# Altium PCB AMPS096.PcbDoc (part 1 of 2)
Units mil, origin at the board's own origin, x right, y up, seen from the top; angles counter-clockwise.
Board outline 2170 x 3820 mil, 2 copper layers (Top Layer, Bottom Layer), stack 62 mil thick; 82 components, 27 nets, 181 pads, 486 vias.
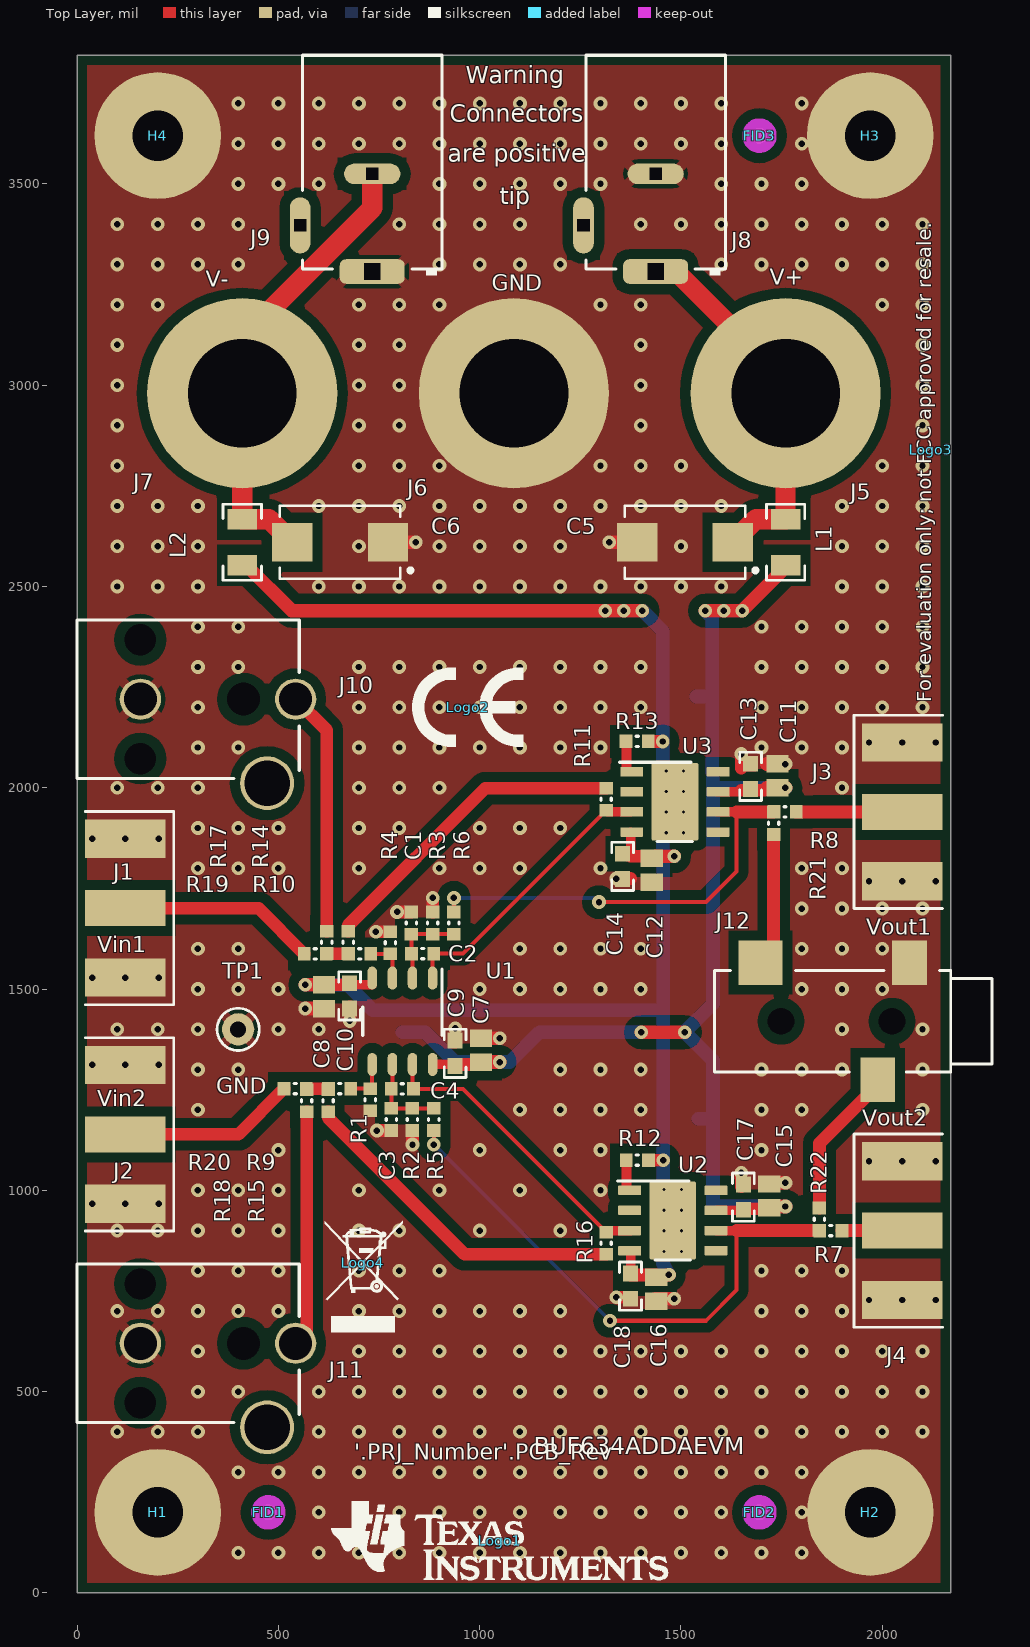
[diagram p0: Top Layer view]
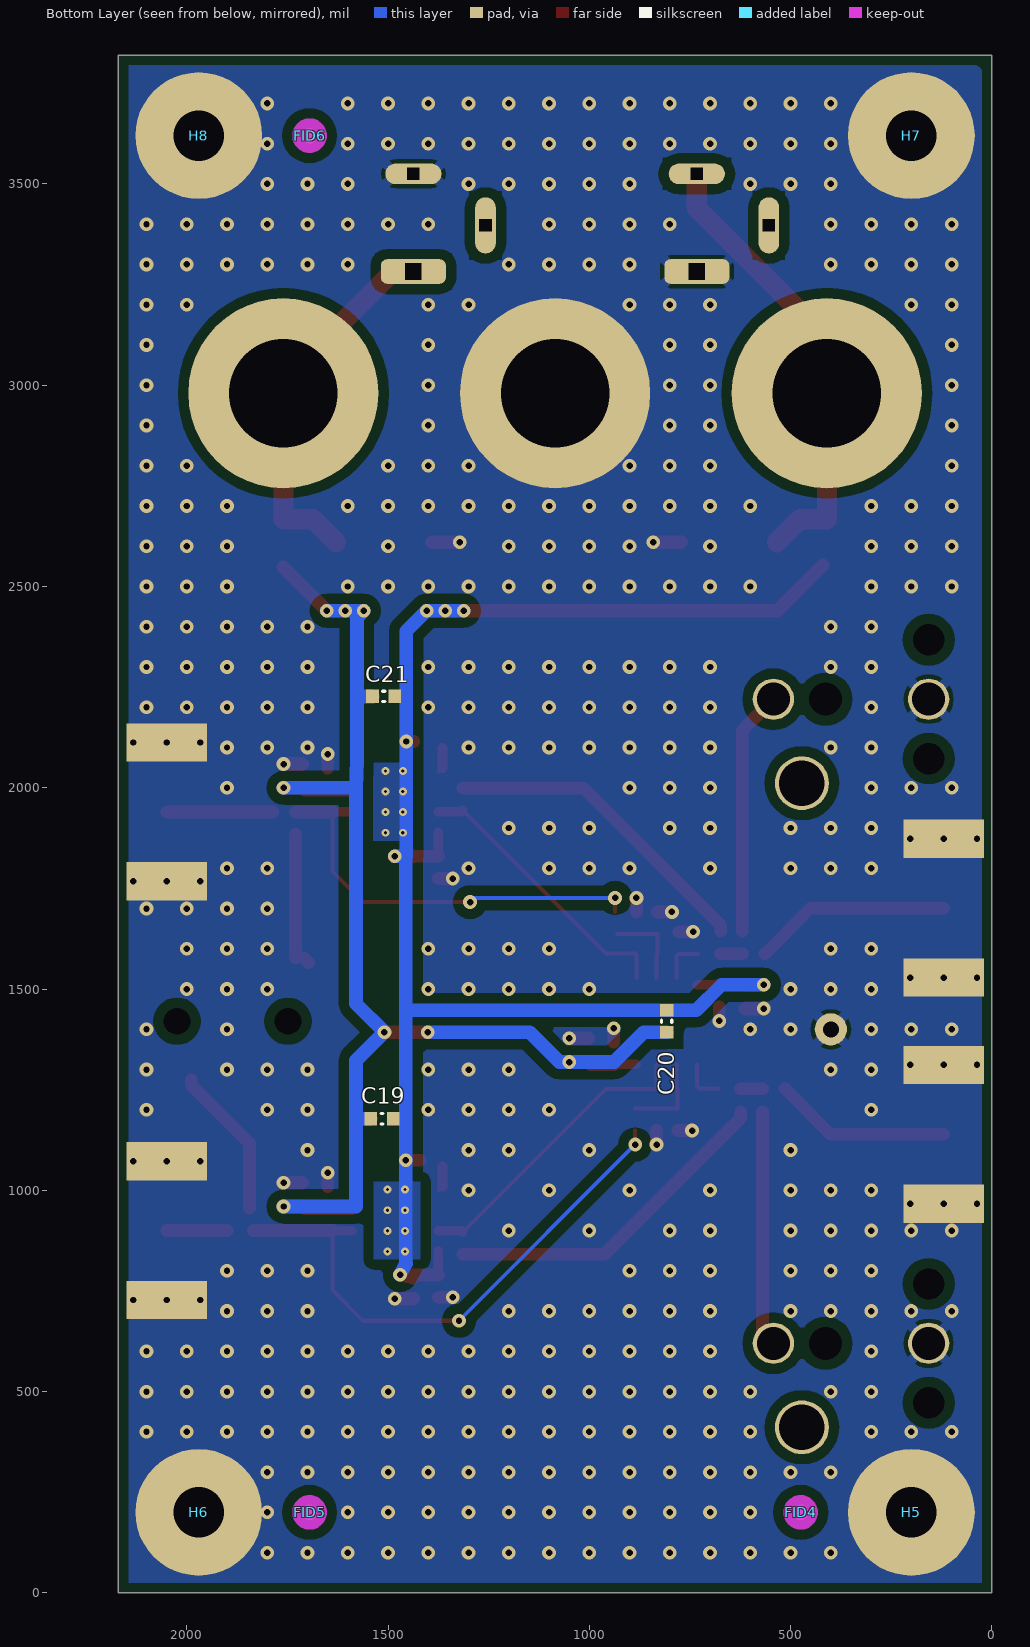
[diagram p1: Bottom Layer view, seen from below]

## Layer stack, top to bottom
Top Solder: solder mask 0.4, Solder Resist, Dk 3.5
Top Layer: signal copper 1.4
Dielectric1: core 59.2, FR-4 High Tg, Dk 4.8
Bottom Layer: signal copper 1.4
Bottom Solder: solder mask 0.4, Solder Resist, Dk 3.5

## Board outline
0,0 2170,0 2170,3820 0,3820

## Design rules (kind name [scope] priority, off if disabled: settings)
AcuteAngle [All] p1: minimum=4.50000000000000E+0001 checktracksonly=FALSE
AssemblyTestPointUsage [All] p1: valid=2
BoardOutlineClearance BoardOutlineClearance_MountingHoles [OnCopper and InComponentClass('Mounting Holes')] p1: gap=40 ignorepadtopadclearanceinfootprint=FALSE
BoardOutlineClearance BoardOutlineClearance_Poly [OnCopper and IsPoly] p2: gap=25 ignorepadtopadclearanceinfootprint=FALSE
BoardOutlineClearance [OnCopper and Not InComponentClass('Logo') and not InComponentClass('FiducialMark') and not InRegion(1000,500,4000,800) and not InPoly] p3: gap=20 ignorepadtopadclearanceinfootprint=FALSE
Clearance Clearance_FiducialMark [InComponent('FID*') vs InComponent('FID*')] p1: gap=0 ignorepadtopadclearanceinfootprint=FALSE
Clearance Clearance_Keepouts [((IsTrack Or IsArc) And Not InPoly) And IsFree and IsKeepOut vs ((IsTrack Or IsArc) And Not InPoly) And IsFree and IsKeepOut] p2: gap=0 ignorepadtopadclearanceinfootprint=FALSE
Clearance Clearance_Poly [InPolygon] p3: gap=25 ignorepadtopadclearanceinfootprint=FALSE except(0: Arc-Hole Track-Hole SMDPad-Hole THPad-Hole Via-Hole Fill-Hole Poly-Hole Region-Hole Text-Hole)
Clearance [All] p4: gap=7.87 ignorepadtopadclearanceinfootprint=FALSE except(0: Arc-Hole Track-Hole SMDPad-Hole THPad-Hole Via-Hole Fill-Hole Poly-Hole Region-Hole Text-Hole)
ComponentClearance ComponentClearance_R7_R22 [InComponent('R7') OR InComponent('R22')] p1: gap=0 collisioncheckmode=3 verticalgap=0 showdistances=FALSE
ComponentClearance ComponentClearance_R8_R21 [InComponent('R8') OR InComponent('R21')] p2: gap=0 collisioncheckmode=3 verticalgap=0 showdistances=FALSE
ComponentClearance ComponentClearance_R9_R16 [InComponent('R9') OR InComponent('R16')] p3: gap=0 collisioncheckmode=3 verticalgap=0 showdistances=FALSE
ComponentClearance ComponentClearance_R10_R15 [InComponent('R10') OR InComponent('R15')] p4: gap=0 collisioncheckmode=3 verticalgap=0 showdistances=FALSE
ComponentClearance ComponentClearance_R17_R19 [InComponent('R17') OR InComponent('R19')] p5: gap=0 collisioncheckmode=3 verticalgap=0 showdistances=FALSE
ComponentClearance ComponentClearance_R18_R20 [InComponent('R18') OR InComponent('R20')] p6: gap=0 collisioncheckmode=3 verticalgap=0 showdistances=FALSE
ComponentClearance ComponentClearance_MountingHoles_FiducialMarks [InComponentClass('Mounting Holes') vs InComponentClass('FiducialMark')] p7: gap=50 collisioncheckmode=3 verticalgap=10 showdistances=FALSE
ComponentClearance ComponentClearance_Shunt [InComponentClass('Header') vs InComponentClass('Shunt')] p8: gap=0 collisioncheckmode=3 verticalgap=0 showdistances=FALSE
ComponentClearance ComponentClearance_Logo [InComponentClass('Logo')] p9: gap=50 collisioncheckmode=3 verticalgap=10 showdistances=FALSE
ComponentClearance ComponentClearance_ScrewToNut [(HasFootprint('NY PMS 440 0025 PH')) vs (HasFootprint('Keystone_1902C'))] p10: gap=5 collisioncheckmode=3 verticalgap=10 showdistances=FALSE
ComponentClearance ComponentClearance_MountingHoles [InComponentClass('Mounting Holes')] p11: gap=50 collisioncheckmode=3 verticalgap=100000 showdistances=FALSE
ComponentClearance ComponentClearance_SmallPassives [HasFootprint('0201*') or HasFootprint('0402*') or HasFootprint('0508') or HasFootprint('0603*') or HasFootprint('0612') or HasFootprint('0805*') or HasFootprint('0815*') or HasFootprint('0830*') or HasFootprint('1206*') or HasFootprint('1210*') or HasFootprint('1808*') or HasFootprint('1812*') or HasFootprint('1825*') or HasFootprint('2010*') or HasFootprint('2220*') or HasFootprint('2225*') or HasFootprint('2512*') or HasFootprint('2728*') or HasFootprint('3518*') or HasFootprint('D0008A*') vs HasFootprint('0201*') or HasFootprint('0402*') or HasFootprint('0508') or HasFootprint('0603*') or HasFootprint('0612') or HasFootprint('0805*') or HasFootprint('0815*') or HasFootprint('0830*') or HasFootprint('1206*') or HasFootprint('1210*') or HasFootprint('1808*') or HasFootprint('1812*') or HasFootprint('1825*') or HasFootprint('2010*') or HasFootprint('2220*') or HasFootprint('2225*') or HasFootprint('2512*') or HasFootprint('2728*') or HasFootprint('3518*') or HasFootprint('D0008A*')] p12: gap=14.96 collisioncheckmode=3 verticalgap=10 showdistances=FALSE
ComponentClearance ComponentClearance_THtoSMT [IsThruComponent vs IsSMTComponent] p13: gap=40 collisioncheckmode=3 verticalgap=30 showdistances=FALSE
ComponentClearance ComponentClearance_THtoTH [IsThruComponent vs IsThruComponent] p14: gap=30 collisioncheckmode=3 verticalgap=30 showdistances=FALSE
ComponentClearance [All] p15: gap=30 collisioncheckmode=3 verticalgap=10 showdistances=FALSE
DiffPairsRouting [All] p1: maxlimit=100 minlimit=10 mostfreqgap=10 toplayer_minwidth=15 toplayer_maxwidth=15 toplayer_prefwidth=15 bottomlayer_minwidth=15 bottomlayer_maxwidth=15 bottomlayer_prefwidth=15 maxuncoupledlength=1000
FabricationTestPointUsage TestPointUsage [All] p1: valid=2 allowmultiple=FALSE
FabricationTestpoint Testpoint [All] p1: side=3 testpointundercomponent=TRUE minsize=40 maxsize=100 preferedsize=60 minholesize=0 maxholesize=40 preferedholesize=32 testpointgrid=1 allowsidetop=TRUE allowsidebottom=TRUE usegrid=TRUE gridtolerance=0.01
FanoutControl Fanout_LCC [IsLCC] p1: bgadir=Out bgaviamode=Centered fanoutstyle=Auto fanoutdirection=Alternating viagrid=1 // Fanout_LCC (Default Rule)
FanoutControl Fanout_BGA [IsBGA] p2: bgadir=Out bgaviamode=Centered fanoutstyle=Auto fanoutdirection=Alternating viagrid=1 // Fanout_BGA (Default Rule)
FanoutControl Fanout_Default [All] p4: bgadir=Out bgaviamode=Centered fanoutstyle=Auto fanoutdirection=Alternating viagrid=1 // Fanout_Default (Default Rule)
FanoutControl Fanout_Small [(CompPinCount < 5)] p5: bgadir=Out bgaviamode=Centered fanoutstyle=Auto fanoutdirection=OutThenIn viagrid=1 // Fanout_Small (Default Rule)
HoleSize [All] p1: absolutevalues=TRUE maxlimit=270 minlimit=7.87 maxpercent=80.000 minpercent=20.000
MinimumAnnularRing MinimumAnnularRing_J8_J9 [(InComponent('J8') OR InComponent('J9'))] p1: minimumring=3.87
MinimumAnnularRing MinimumAnnularRing_ThermalPadVias [IsVia and InAnyComponent] p2: minimumring=5.91
MinimumAnnularRing [All] p3: minimumring=8
MinimumSolderMaskSliver MinimumSolderMaskSliver_Logo [InComponentClass('Logo') vs InComponentClass('Logo')] p1: minsoldermaskwidth=0.7
MinimumSolderMaskSliver [All] p2: minsoldermaskwidth=3.94
PlaneConnect [All] p1: planeconnectstyle=Direct reliefexpansion=10 reliefentries=4 reliefconductorwidth=10 reliefairgap=10
PolygonConnect PolygonConnect_Keystone5001 [HasFootprint('Keystone_6095')] p1: connectstyle=Direct reliefconductorwidth=10 reliefentries=4 polygonreliefangle="90 Angle" airgapwidth=10
PolygonConnect "PolygonConnect_NY PMS 440 0025 PH" [HasFootprint('NY PMS 440 0025 PH')] p2: connectstyle=Direct reliefconductorwidth=10 reliefentries=4 polygonreliefangle="90 Angle" airgapwidth=10
PolygonConnect [All] p3: thpad.connectstyle=Relief thpad.reliefconductorwidth=25 thpad.reliefentries=4 thpad.polygonreliefangle="45 Angle" thpad.airgapwidth=10 smdpad.connectstyle=Direct smdpad.reliefconductorwidth=10 smdpad.reliefentries=4 smdpad.polygonreliefangle="90 Angle" smdpad.airgapwidth=10 via.connectstyle=Direct via.reliefconductorwidth=10 via.reliefentries=4 via.polygonreliefangle="90 Angle" via.airgapwidth=10
RoutingVias ThermalPadVias [IsVia and InAnyComponent] p1: holewidth=7.87 width=19.68 viastyle="Through Hole" minholewidth=7.87 minwidth=19.68 maxholewidth=12.99 maxwidth=23.62
RoutingVias [All] p2: holewidth=16 width=34 viastyle="Through Hole" minholewidth=7.87 minwidth=26 maxholewidth=40 maxwidth=65
SilkToBoardRegionClearance [Not ((IsComment or IsDesignator) And (Hide <> 'False')) and not InRegion(1000,500,4000,800)] p1:
SilkToSilkClearance SilkToSilkClearance_Pb-FreeLogo [(HasFootprint('Pb-Free_Overlay_Medium') OR HasFootprint('Pb-Free_Overlay_Small')) vs (HasFootprint('Pb-Free_Overlay_Medium') OR HasFootprint('Pb-Free_Overlay_Small'))] p1: silktosilkclearance=0
SilkToSilkClearance [All] p2: silktosilkclearance=4
SilkToSolderMaskClearance SilkToComponentPadClearance [(IsPad or IsFill or IsRegion) and InAnycomponent] p1: minsilkscreentomaskgap=5 clearancetoexposedcopper=TRUE
SilkToSolderMaskClearance "Silk to Solder Mask Opening" [All] p2: minsilkscreentomaskgap=4 clearancetoexposedcopper=FALSE
SolderMaskExpansion [All] p1: expansion=1.97
Width [All] p1: maxlimit=100 minlimit=6 preferedwidth=10 checkconnectedcopper=TRUE
15 further rules are at their usual default settings.

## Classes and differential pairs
component class AMPS096: C1 C2 C3 C4 C5 C6 C7 C8 C9 C10 C11 C12 C13 C14 C15 C16 C17 C18 C19 C20 C21 J1 J2 J3 J4 J5 J6 J7 J8 J9 J10 J11 J12 J? L1 L2 R1 R2 R3 R4 R5 R6 R7 R8 R9 R10 R11 R12 R13 R14 R15 R16 R17 R18 R19 R20 R21 R22 TP1 U1 U2 U3 U?
component class "Mounting Holes": H1 H2 H3 H4
component class Logo: Logo1
component class "AMPS096 Hardware": FID1 FID2 FID3 FID4 FID5 FID6 H1 H2 H3 H4 H5 H6 H7 H8 Logo1 Logo2 Logo3 Logo4 ZZ2 ZZ3 ZZ4
component class FiducialMark: FID1 FID2 FID3 FID4 FID5 FID6
component class AssemblyNote: ZZ2 ZZ3 ZZ4

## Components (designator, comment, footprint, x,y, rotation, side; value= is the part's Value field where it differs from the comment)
C1 "C0603C100F5GAC7867" 0603L 830.44,1664 r90 top value=10pF
C2 "C0603C100F5GAC7867" 0603L 858,1588 r0 top value=10pF
C3 "C0603C100F5GAC7867" 0603L 780.44,1176 r270 top value=10pF
C4 "C0603C100F5GAC7867" 0603L 808,1252 r0 top value=10pF
C5 "T495D685K050ATE300" 7343-31 1510,2610 r180 top value=6.8uF
C6 "T495D685K050ATE300" 7343-31 653.03,2610 r180 top value=6.8uF
C7 "08055C105KAT2A" 0805L 1003,1348.15 r90 top value=1uF
C8 "08055C105KAT2A" 0805L 613,1481.03 r270 top value=1uF
C9 "C1608X5R1H104K080AA" 0603 939,1340.28 r90 top value=0.1uF
C10 "C1608X5R1H104K080AA" 0603 677,1482.99 r270 top value=0.1uF
C11 "08055C105KAT2A" 0805L 1739.77,2029.8 r90 top value=1uF
C12 "08055C105KAT2A" 0805L 1427.17,1795 r270 top value=1uF
C13 "C1608X5R1H104K080AA" 0603 1673.1,2028.12 r90 top value=0.1uF
C14 "C1608X5R1H104K080AA" 0603 1355,1804.53 r270 top value=0.1uF
C15 "08055C105KAT2A" 0805L 1719.17,986.17 r90 top value=1uF
C16 "08055C105KAT2A" 0805L 1438.58,754.06 r270 top value=1uF
C17 "C1608X5R1H104K080AA" 0603 1655,983.15 r90 top value=0.1uF
C18 "C1608X5R1H104K080AA" 0603 1374.72,762 r270 top value=0.1uF
C19 "06031C103KAT2A" 0603L 1515,1177.76 r180 bottom value=0.01uF
C20 "06031C103KAT2A" 0603L 808,1420 r90 bottom value=0.01uF
C21 "06031C103KAT2A" 0603L 1510.91,2226.92 r180 bottom value=0.01uF
FID1 "Fiducial" Fiducial10-20 475,200 r0 top
FID2 "Fiducial" Fiducial10-20 1695,200 r0 top
FID3 "Fiducial" Fiducial10-20 1695,3620 r0 top
FID4 "Fiducial" Fiducial10-20 475,200 r90 bottom
FID5 "Fiducial" Fiducial10-20 1695,200 r90 bottom
FID6 "Fiducial" Fiducial10-20 1695,3620 r90 bottom
H1 "NY PMS 440 0025 PH" "NY PMS 440 0025 PH" 200,200 r0 top
H2 "NY PMS 440 0025 PH" "NY PMS 440 0025 PH" 1970,200 r0 top
H3 "NY PMS 440 0025 PH" "NY PMS 440 0025 PH" 1970,3620 r0 top
H4 "NY PMS 440 0025 PH" "NY PMS 440 0025 PH" 200,3620 r0 top
H5 "1902C" Keystone_1902C 200,200 r180 bottom
H6 "1902C" Keystone_1902C 1970,200 r180 bottom
H7 "1902C" Keystone_1902C 200,3620 r180 bottom
H8 "1902C" Keystone_1902C 1970,3620 r180 bottom
J1 "Vin1" Johnson_142-0701-801_NoVias 120,1701 r90 top
J2 "Vin2" Johnson_142-0701-801_NoVias 120,1139 r90 top
J3 "Vout1" Johnson_142-0701-801_NoVias 2050,1940 r270 top
J4 "Vout2" Johnson_142-0701-801_NoVias 2050,900 r270 top
J5 "V+" Keystone_6095 1760,2980 r0 top
J6 "GND" Keystone_6095 1085,2980 r0 top
J7 "V-" Keystone_6095 410,2980 r0 top
J8 "EJ508A" Memory_EJ508A 1437,3397 r180 top
J9 "EJ508A" Memory_EJ508A 733,3397 r180 top
J10 "970" Keystone_970 157,2220 r0 top
J11 "971" Keystone_971 157,620 r0 top
J12 "SJ-3523-SMT" CUI_SJ-3523-SMT 1882.6,1420 r180 top
L1 "HI1206N800R-10" 1206 1760,2610 r270 top value="80 ohm"
L2 "HI1206N800R-10" 1206 410,2610 r270 top value="80 ohm"
Logo1 "Texas Instruments" TI_Stacked_Overlay_Small 1050,130 r0 top
Logo2 "CE Mark" CE_Mark_5mm 970,2200 r0 top
Logo3 "FCC disclaimer" FCC_disclaimer 2120,2840 r90 top
Logo4 "WEEE logo" WEEE_Minimum 710,820 r0 top
R1 "CRCW060349R9FKEA" 0603L 728,1225 r90 top value=49.9
R2 "CRCW06031K00JNEA" 0603L 833,1176 r90 top value=1.0k
R3 "CRCW06031K00JNEA" 0603L 883,1664 r270 top value=1.0k
R4 "CRCW060349R9FKEA" 0603L 778,1615 r90 top value=49.9
R5 "CRCW06031K00JNEA" 0603L 886,1176 r270 top value=1.0k
R6 "CRCW06031K00JNEA" 0603L 936,1664 r90 top value=1.0k
R7 "CRCW060349R9FKEA" 0603L 1872.47,900 r180 top value=49.9
R8 "CRCW060349R9FKEA" 0603L 1758.47,1940 r180 top value=49.9
R9 "CRCW06030000Z0EA" 0603L 652,1252.56 r180 top value=0
R10 "CRCW06030000Z0EA" 0603L 702,1587.44 r180 top value=0
R11 "CRCW06030000Z0EA" 0603L 1314,1971.5 r270 top value=0
R12 "CRCW06030000Z0EA" 0603L 1391.69,1075 r180 top value=0
R13 "CRCW06030000Z0EA" 0603L 1390.91,2115 r180 top value=0
R14 "CRCW06030000Z0EA" 0603L 673.53,1615.91 r270 top value=0
R15 "CRCW06030000Z0EA" 0603L 623.53,1222.53 r90 top value=0
R16 "CRCW06030000Z0EA" 0603L 1314,868.5 r90 top value=0
R17 "CRCW06030000Z0EA" 0603L 620,1615.91 r270 top value=0
R18 "CRCW06030000Z0EA" 0603L 570,1222.53 r270 top value=0
R19 "CRCW06030000Z0EA" 0603L 591.53,1587.44 r180 top value=0
R20 "CRCW06030000Z0EA" 0603L 541.53,1252.56 r180 top value=0
R21 "CRCW060349R9FKEA" 0603L 1730,1911.53 r270 top value=49.9
R22 "CRCW060349R9FKEA" 0603L 1844,928.47 r270 top value=49.9
TP1 "GND" Keystone5001 400,1400 r90 top
U1 "OPA2810IDR" D0008A_N 808,1420 r270 top
U2 "BUF634AIDDAR" DDA0008B_N 1479.73,925 r0 top
U3 "BUF634AIDDAR" DDA0008B_N 1484.95,1965 r0 top
ZZ2 "These assemblies are ESD sensitive, ESD precautions shall be observed." AssemblyNote 175,4129.11 r0 top
ZZ3 "These assemblies must be clean and free from flux and all contaminants. Use of no clean flux is not acceptable." AssemblyNote 175,4040.56 r0 top
ZZ4 "These assemblies must comply with workmanship standards IPC-A-610 Class 2, unless otherwise specified." AssemblyNote 175,3952 r0 top

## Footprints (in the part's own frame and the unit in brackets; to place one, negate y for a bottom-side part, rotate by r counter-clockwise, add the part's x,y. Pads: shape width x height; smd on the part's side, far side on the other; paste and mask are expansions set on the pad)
0603 [mm] "0603 from SM-752 data"
  rect 1x0.95 smd: 1(-0.8,0) 2(0.8,0)
  silkscreen extent -1.52,-0.69 1.52,0.69, body extent -0.87,-0.47 0.87,0.47, height 1
0603L [mm] "0603 from SM-752 data"
  rect 0.8x0.85 smd: 1(-0.7,0) 2(0.7,0)
  silkscreen extent -0.07,-0.33 0.07,0.33, body extent -0.87,-0.47 0.87,0.47, height 1
0805L [mm] "0805 from SM-752 data"
  rect 1.1x1.4 smd: 1(-0.75,0) 2(0.75,0)
  body extent -1.1,-0.72 1.1,0.72, height 1.45
1206 [mm] "1206 from SM-752 data"
  rect 1.3x1.85 smd: 1(-1.45,0) 2(1.45,0)
  silkscreen extent -2.4,-1.21 2.4,1.21, body extent -1.7,-0.9 1.7,0.9, height 1.35
7343-31 [mm] "Medium Density based on Kemet T495 dimensions"
  rect 2.55x2.45 smd: 1(-3.025,0) 2(3.025,0)
  silkscreen extent -4.56,-2.3 3.8,2.3, body extent -3.8,-2.3 3.8,2.3, height 3.1
AssemblyNote [mil] "Assembly Note"
CE_Mark_5mm [mil] "Minimum text height for CE Mark"
  silkscreen extent -138,-98 138,98
CUI_SJ-3523-SMT [mm] "CUI recommended land pattern Rev C CUI_SJ-3523-SMT_Datasheet.pdf"
  rect 2.2x2.8 smd: 1(-4.7,-3.7) 3(-2.7,3.7)
  rect 2.8x2.8 smd: 2(4.7,-3.7)
  round 0 hole 1.7 unplated: 4(-3.6,0) 5(3.4,0)
  silkscreen extent -9.9,-3.2 7.6,3.2, body extent -9.6,-4.5 7.4,4.5, height 5.12
D0008A_N [mm] "SOIC, 8-Leads, Body 4.9x3.9mm, Pitch 1.27mm, IPC Medium Density"
  oval 1.45x0.6 smd: 1(-2.725,1.905) 2(-2.725,0.635) 3(-2.725,-0.635) 4(-2.725,-1.905) 5(2.725,-1.905) 6(2.725,-0.635) 7(2.725,0.635) 8(2.725,1.905)
  silkscreen extent -3.3,-2.5 0.9,2.5, body extent -3,-2.45 3,2.45, height 1.63
DDA0008B_N [mm] "SOIC, 8-Leads, Body 4.9x3.9mm, Pitch 1.27mm, Exposed Pad, IPC Medium Density"
  rrect17% 1.45x0.6 smd: 1(-2.725,1.905) 2(-2.725,0.635) 3(-2.725,-0.635) 4(-2.725,-1.905) 5(2.725,-1.905) 6(2.725,-0.635) 7(2.725,0.635) 8(2.725,1.905)
  rrect7% 2.95x4.9 smd paste-1.5 mask-1.5: 9(0,0)
  rrect4% 2.71x3.4 on Top Paste: 9(0,0)
  rrect4% 2.71x3.4 on Top Solder: 9(0,0)
  silkscreen extent -3.5,-2.5 1.1,2.5, body extent -3.01,-2.45 3.01,2.45, height 1.57
FCC_disclaimer [mil]
Fiducial10-20 [mm]
  round 1 smd mask+0.5: 1(0,0)
  Top Layer keep-out circle w1.178: c0,0 r0.5
Johnson_142-0701-801_NoVias [mil] "Johnson Components recommended land pattern"
  rect 90x200 smd: 1(0,0)
  rect 95x200 smd: 2(-172.5,0) 3(172.5,0)
  rect 95x200 smd far side: 4(-172.5,0) 5(172.5,0)
  silkscreen extent -240,-120 240,100, body extent -190,-92 190,480, height 165
Keystone5001 [mil] "For Keystone 500x miniature loop terminals"
  round 80 hole 40: 1(0,0)
  silkscreen extent -52,-52 52,52, body extent -49,-49 49,49, height 182
Keystone_970 [mm] "PC Mount Phono Jack-White, TH"
  round 2.6 hole 2.08: 1(0,0) 3(9.8,0)
  round 3.4 hole 2.87: 4(8,-5.3)
  round 0 hole 1.98 unplated: M1(0,3.745) M2(0,-3.745)
  round 0 hole 2.08 unplated: M3(6.5,0)
  silkscreen extent -3.99,-5.01 10.03,5.01, body extent -13.33,-5.43 10.03,5.01, height 13.02
Keystone_971 [mm] "PC Mount Phono Jack-Red, TH"
  round 2.6 hole 2.08: 1(0,0) 3(9.8,0)
  round 3.4 hole 2.87: 4(8,-5.3)
  round 0 hole 1.98 unplated: M1(0,3.745) M2(0,-3.745)
  round 0 hole 2.08 unplated: M3(6.5,0)
  silkscreen extent -3.99,-5.01 10.03,5.01, body extent -13.31,-5.44 10.05,5, height 13.02
Keystone_1902C [mil] "Hex Standoff, 4-40 threaded, nylon"
  round 1 on Mech4: 0(0,0)
  body extent -145,-126 146,126, height 501
Keystone_6095 [mm] "Banana Jack Uninsulated Standard Type"
  round 12 hole 6.858: 1(0,0)
  body extent -4.77,-5.5 4.75,5.49, height 2.39
Memory_EJ508A [mm] "Power Jack, 2.1x5.5mm, R/A, TH"
  rrect50% 4.1x1.55 hole 1.02 square: 1(0,2.91)
  oval 3.55x1.3 hole 0.76 square: 2(0,-3.25)
  oval 1.3x3.55 hole 0.76 square: 3(4.55,0)
  silkscreen extent -4.4,-10.74 4.4,3.16, body extent -4.4,-10.74 4.7,3.68, height 10.85
"NY PMS 440 0025 PH" [mm] "4-40 nylon screw and mounting hole"
  round 8 hole 3.2: 1(0,0)
  body extent -3.3,-3.3 3.3,3.3, height 2.69
TI_Stacked_Overlay_Small [mil]
  silkscreen extent -418,-98 418,98
WEEE_Minimum [mil] "WEEElie bin"
  silkscreen extent -95,-172 99,104

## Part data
C1 C2 C3 C4: library part CMP-0006838-4, "CAP, CERM, 10 pF, 50 V, +/- 1%, C0G/NP0, 0603", Cap_Case=0603, Manufacturer=Kemet, Supplier Part Number 1=399-9958-1-ND, TempCo=C0G/NP0, Tolerance_%=1%, Value1=Unknown, Value2=50V, ValueDisplayed=10pF
C5 C6: library part CMP-0011788-2, "CAP, TA, 6.8 uF, 50 V, +/- 10%, 0.3 ohm, SMD", Cap_Case=D, Manufacturer=Kemet, Supplier Part Number 1=399-3888-1-ND, Tolerance_%=10%, Value1="0.3 ohm", Value2=50V, ValueDisplayed=6.8uF
C7 C8 C11 C12 C15 C16: library part CMP-0007634-2, "CAP, CERM, 1 uF, 50 V, +/- 10%, X7R, 0805", Cap_Case=0805, Manufacturer=AVX, Supplier Part Number 1=478-7956-1-ND, TempCo=X7R, Tolerance_%=10%, Value1=Unknown, Value2=50V, ValueDisplayed=1uF
C9 C10 C13 C14 C17 C18: library part CMP-0007010-3, "CAP, CERM, 0.1 uF, 50 V, +/- 10%, X5R, 0603", Cap_Case=0603, Manufacturer=TDK, Supplier Part Number 1=445-7456-1-ND, TempCo=X5R, Tolerance_%=10%, Value1="0.0296 ohm", Value2=50V, ValueDisplayed=0.1uF
C19 C20 C21: library part CMP-0006727-4, "CAP, CERM, 0.01 uF, 100 V, +/- 10%, X7R, 0603", Cap_Case=0603, Manufacturer=AVX, Supplier Part Number 1=478-1205-1-ND, TempCo=X7R, Tolerance_%=10%, Value1="0.098 ohm", Value2=100V, ValueDisplayed=0.01uF
FID1 FID2 FID3 FID4 FID5 FID6: library part CMP-0077181-1, "Fiducial mark.  There is nothing to buy or mount.", Manufacturer=N/A
H1 H2 H3 H4: library part CMP-0003617-1, "Machine Screw, Round, #4-40 x 1/4, Nylon, Philips panhead", Manufacturer="B&F Fastener Supply", Supplier Part Number 1=H542-ND
H5 H6 H7 H8: library part CMP-0003610-1, "Standoff, Hex, 0.5\"L #4-40 Nylon", Manufacturer=Keystone, Supplier Part Number 1=36-1902C-ND
J1 J2 J3 J4: library part CMP-0055828-1, "Connector, End launch SMA, 50 ohm, SMT", Manufacturer="Cinch Connectivity", PartNumber=142-0701-801, Supplier Part Number 1=J502-ND
J5 J6 J7: library part CMP-0055169-2, "Standard Banana Jack, Uninsulated", Manufacturer=Keystone, PartNumber=6095, Supplier Part Number 1=36-6095-ND
J8 J9: library part CMP-0055800-1, "Power Jack, 2.1x5.5mm, R/A, TH", Color=Black, Current_A=5A, Manufacturer="Memory Protection Devices", Supplier Part Number 1=EJ508A-ND, Voltage_V=12V
J10: library part CMP-0055175-2, "RCA Jack, White, R/A, TH", Manufacturer=Keystone, Supplier Part Number 1=36-970-ND
J11: library part CMP-0055174-2, "RCA Jack, Red, R/A, TH", Manufacturer=Keystone, Supplier Part Number 1=36-971-ND
J12: library part CMP-0074907-1, "Audio Jack, 3.5mm, Stereo, R/A, SMT", Manufacturer="CUI Inc.", Supplier Part Number 1=CP-3523SJCT-ND
L1 L2: library part CMP-0003379-1, "Ferrite Bead, 80 ohm @ 100 MHz, 3 A, 1206", Manufacturer="Laird-Signal Integrity Products", Supplier Part Number 1=240-2409-1-ND, Value1="0.035 ohm", Value2=3A, ValueDisplayed="80 ohm"
Logo1: library part CMP-0074838-1, "Texas Instrument Corporate Signature"
Logo2: library part CMP-0074844-1
Logo3: library part CMP-0074847-1, "FCC_disclaimer"
Logo4: library part CMP-0074769-1
R1 R4 R7 R8 R21 R22: library part CMP-0022448-4, "RES, 49.9, 1%, 0.1 W, AEC-Q200 Grade 0, 0603", Manufacturer=Vishay-Dale, Power_W=100mW, Supplier Part Number 1=541-49.9HCT-ND, TempCo="100 ppm/C", Tolerance_%=1%, Value2=0.1W, Value_Code=49R9, ValueDisplayed=49.9
R2 R3 R5 R6: library part CMP-0025729-4, "RES, 1.0 k, 5%, 0.1 W, AEC-Q200 Grade 0, 0603", Manufacturer=Vishay-Dale, Power_W=100mW, Supplier Part Number 1=541-1.0KGCT-ND, TempCo="200 ppm/C", Tolerance_%=5%, Value2=0.1W, Value_Code=1k00, ValueDisplayed=1.0k
R9 R10 R11 R12 R13 R14 R15 R16 R17 R18 R19 R20: library part CMP-0025697-4, "RES, 0, 5%, 0.1 W, AEC-Q200 Grade 0, 0603", Manufacturer=Vishay-Dale, Power_W=100mW, Supplier Part Number 1=541-0.0GCT-ND, TempCo="200 ppm/C", Tolerance_%=5%, Value2=0.1W, Value_Code=0000, ValueDisplayed=0
TP1: library part CMP-0055138-1, "Test Point, Miniature, Black, TH", Color=Black, Manufacturer=Keystone, PartNumber=5001, Supplier Part Number 1=36-5001-ND
U1: library part CMP-0085273-1, "High Performance Low Cost Rail-to-Rail Input/Output HV FET Op Amps, D0008A (SOIC-8)", Alternate Manufacturer="Texas Instruments", Alternate PartNumber=OPA2810IDT, Operating Temperature Range="-40 to 125 C", Rating=Catalog
U2 U3: library part CMP-0861073-1, "36-V, 210-MHz, 250-mA Output, High-Speed Buffer, DDA0008B (HSOIC-8)", Alternate Manufacturer="Texas Instruments", Alternate PartNumber=BUF634AIDDAT, Operating Temperature Range="-40 to 125 C", Rating=Catalog
ZZ2: library part CMP-0077236-1
ZZ3: library part CMP-0077237-1
ZZ4: library part CMP-0077238-1

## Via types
v1: diameter 34, hole 16, Top Layer to Bottom Layer, tented both sides, 470 vias
v2: diameter 19.68, hole 7.87, Top Layer to Bottom Layer, tented both sides, 8 vias
v3: diameter 19.68, hole 7.87, Top Layer to Bottom Layer, 8 vias

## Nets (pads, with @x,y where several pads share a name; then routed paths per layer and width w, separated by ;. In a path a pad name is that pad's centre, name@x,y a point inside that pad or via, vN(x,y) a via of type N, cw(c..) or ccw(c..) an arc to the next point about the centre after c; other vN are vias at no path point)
GND: C1.2 C3.2 C5.2 C6.1 C7.2 C8.2 C9.2 C10.2 C11.2 C12.2 C13.2 C14.2 C15.2 C16.2 C17.2 C18.2 H1.1 H2.1 H3.1 H4.1 J1.2 J1.3 J1.4 J1.5 J2.2 J2.3 J2.4 J2.5 J3.2 J3.3 J3.4 J3.5 J4.2 J4.3 J4.4 J4.5 J6.1 J8.2 J9.1 J10.1 J11.1 J12.1 R1.1 R2.1 R3.1 R4.2 TP1.1 | length 757.8
  Top Layer w31.5: v1(677,1420.72) C10.2@677,1455.43 ; v1(742.3,1642.56) R4.2@778,1642.56 ; v1(744.74,1148.44) C3.2@780.44,1148.44 ; v1(794.74,1691.56) C1.2@830.44,1691.56 ; v1(833,1113.72) R2.1@833,1148.44 ; R3.1@883,1691.56 v1(883,1726.28) ; C9.2@939,1367.83 v1(939,1402.55) ; v1(1339.02,734.44) C18.2@1374.72,734.44 ; v1(1339.02,1774.44) 1374.72,1774.44 ; C17.2@1650,1009.05 v1(1650,1043.77) ; 1650,2049.05 v1(1650,2083.77)
  Top Layer w34: v1(566.47,1451.5) C8.2@613,1451.5 ; C6.1@772.13,2610 v1(841.29,2610) ; C7.2@1003,1377.68 v1(1049.53,1377.68) ; v1(1321.74,2610) C5.2@1390.91,2610 ; C16.2@1437,730.5 v1(1483.53,730.5) ; C15.2@1713,1018.9 v1(1759.53,1018.9) ; C11.2@1713,2058.9 v1(1759.53,2058.9)
  other v1: 400,100 500,100 600,100 700,100 800,100 900,100 1000,100 1100,100 1200,100 1300,100 1400,100 1500,100 1600,100 1700,100 1800,100 600,200 700,200 800,200 900,200 1000,200 1100,200 1200,200 1300,200 1400,200 1500,200 1600,200 1800,200 400,300 500,300 600,300 700,300 800,300 900,300 1000,300 1100,300 1200,300 1300,300 1400,300 1500,300 1600,300 1700,300 1800,300 100,400 200,400 300,400 600,400 700,400 800,400 900,400 1000,400 1100,400 1200,400 1300,400 1400,400 1500,400 1600,400 1700,400 1800,400 1900,400 2000,400 2100,400 300,500 400,500 600,500 700,500 800,500 900,500 1000,500 1100,500 1200,500 1300,500 1400,500 1500,500 1600,500 1700,500 1800,500 1900,500 2000,500 2100,500 300,600 700,600 800,600 900,600 1000,600 1100,600 1200,600 1300,600 1400,600 1500,600 1600,600 1700,600 1800,600 1900,600 2000,600 2100,600 100,700 200,700 300,700 400,700 500,700 700,700 800,700 900,700 1000,700 1100,700 1200,700 1700,700 1800,700 1900,700 1967,727.5 2050,727.5 2133,727.5 300,800 400,800 500,800 700,800 800,800 900,800 1700,800 1800,800 1900,800 100,900 200,900 300,900 400,900 500,900 700,900 800,900 1000,900 1200,900 37,966.5 120,966.5 203,966.5 300,1000 400,1000 500,1000 700,1000 900,1000 1100,1000 1300,1000 1967,1072.5 2050,1072.5 2133,1072.5 500,1100 1000,1100 1200,1100 1300,1100 1700,1100 300,1200 1100,1200 1200,1200 1300,1200 1400,1200 1700,1200 1800,1200 2100,1200 300,1300 400,1300 1200,1300 1300,1300 1400,1300 1700,1300 1800,1300 1900,1300 2100,1300 37,1311.5 120,1311.5 203,1311.5 100,1400 200,1400 300,1400 500,1400 600,1400 1900,1400 2100,1400 300,1500 400,1500 500,1500 1000,1500 1100,1500 1200,1500 1300,1500 1400,1500 1800,1500 1900,1500 2000,1500 37,1528.5 120,1528.5 203,1528.5 300,1600 400,1600 1100,1600 1200,1600 1300,1600 1400,1600 1800,1600 1900,1600 2000,1600 1800,1700 1900,1700 2000,1700 2100,1700 1967,1767.5 2050,1767.5 2133,1767.5 300,1800 400,1800 500,1800 700,1800 900,1800 1000,1800 1100,1800 1300,1800 1800,1800 1900,1800 37,1873.5 120,1873.5 203,1873.5 300,1900 400,1900 500,1900 700,1900 800,1900 1000,1900 1100,1900 1200,1900 100,2000 200,2000 300,2000 700,2000 800,2000 900,2000 1900,2000 300,2100 400,2100 700,2100 800,2100 900,2100 1000,2100 1100,2100 1200,2100 1300,2100 1700,2100 1800,2100 1900,2100 1967,2112.5 2050,2112.5 2133,2112.5 300,2200 700,2200 800,2200 900,2200 1000,2200 1100,2200 1200,2200 1300,2200 1400,2200 1700,2200 1800,2200 1900,2200 2000,2200 2100,2200 300,2300 400,2300 700,2300 800,2300 900,2300 1000,2300 1100,2300 1200,2300 1300,2300 1400,2300 1700,2300 1800,2300 1900,2300 2000,2300 2100,2300 300,2400 400,2400 1700,2400 1800,2400 1900,2400 2000,2400 2100,2400 100,2500 200,2500 300,2500 600,2500 700,2500 800,2500 900,2500 1000,2500 1100,2500 1200,2500 1300,2500 1400,2500 1500,2500 1600,2500 1900,2500 2000,2500 2100,2500 100,2600 200,2600 300,2600 700,2600 900,2600 1000,2600 1100,2600 1200,2600 1500,2600 1900,2600 2000,2600 2100,2600 100,2700 200,2700 300,2700 600,2700 700,2700 800,2700 900,2700 1000,2700 1100,2700 1200,2700 1300,2700 1400,2700 1500,2700 1600,2700 1900,2700 2000,2700 2100,2700 100,2800 700,2800 800,2800 900,2800 1300,2800 1400,2800 1500,2800 2000,2800 2100,2800 100,2900 700,2900 800,2900 1400,2900 2100,2900 100,3000 700,3000 800,3000 1400,3000 2100,3000 100,3100 700,3100 800,3100 1400,3100 2100,3100 100,3200 200,3200 700,3200 800,3200 900,3200 1300,3200 1400,3200 2000,3200 2100,3200 100,3300 200,3300 300,3300 400,3300 900,3300 1000,3300 1100,3300 1200,3300 1600,3300 1700,3300 1800,3300 1900,3300 2000,3300 2100,3300 100,3400 200,3400 300,3400 400,3400 800,3400 900,3400 1000,3400 1100,3400 1400,3400 1500,3400 1600,3400 1700,3400 1800,3400 1900,3400 2000,3400 2100,3400 400,3500 500,3500 600,3500 900,3500 1000,3500 1100,3500 1200,3500 1300,3500 1600,3500 1700,3500 1800,3500 400,3600 500,3600 600,3600 700,3600 800,3600 900,3600 1000,3600 1100,3600 1200,3600 1300,3600 1400,3600 1500,3600 1600,3600 1800,3600 400,3700 500,3700 600,3700 700,3700 800,3700 900,3700 1000,3700 1100,3700 1200,3700 1300,3700 1400,3700 1500,3700 1600,3700 1800,3700
NetC1_1: C1.1 C2.1 R3.2 R6.1 U1.2 | length 211.2
  Top Layer w10: U1.2@833,1527.28 833,1585.44 C2.1@830.44,1588 C1.1@830.44,1636.44 R3.2@883,1636.44 R6.1@931.44,1636.44
NetC2_2: C2.2 R11.2 U1.1 U3.3 | length 700
  Top Layer w10: U1.1@883,1527.28 883,1585.44 C2.2@885.56,1588 958.06,1588 R11.2@1314,1943.94
  Top Layer w23.62: R11.2@1314,1943.94 1317.94,1940 U3.3@1374.72,1940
